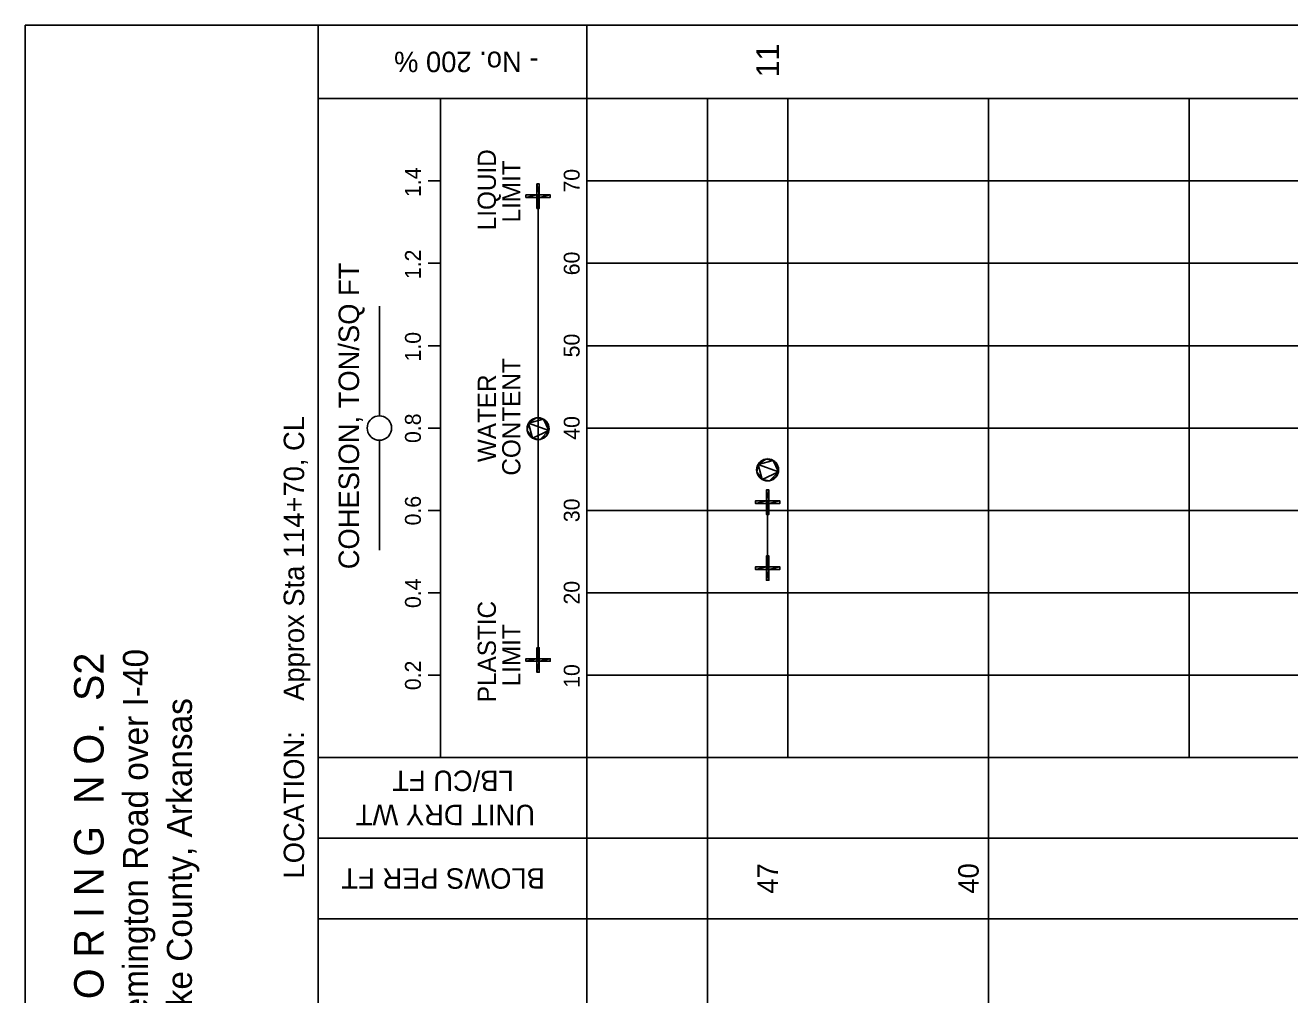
# Model space of a CAD drawing. Extents: x 1313964 to 1316843, y 2087046 to 2096619.
# Drawn here: x 1314075.31 to 1314106.79, y 2089946.89 to 2089971.04 of the extents above; entities that cross this region are included whole.
import ezdxf

# ---------------------------------------------------------------- set-up
doc = ezdxf.new("R2010")
doc.units = 0
doc.layers.add('B-Sub-Contour', color=7, linetype='Continuous')
doc.layers.add('Default', color=7, linetype='Continuous')

# ---------------------------------------------------------------- blocks, each defined once
blk = doc.blocks.new('POINT_DISPLAY')
at = {"layer": 'Default'}
blk.add_line((0, 0), (0, 0), dxfattribs=at)
blk = doc.blocks.new('DMK_101')
at = {"layer": 'Default'}
for points in [[(-14269.212, 2386.584), (-14476.476, 0), (-14269.212, -2386.584), (-14269.212, 2386.584)], [(-12638.532, 6858), (-13653.516, 4690.872), (-14269.212, 2386.584), (-12638.532, 6858)], [(-12638.532, 6858), (-14269.212, 2386.584), (-14269.212, -2386.584), (-12638.532, 6858)], [(-12638.532, 6858), (-14269.212, -2386.584), (-3147.06, -13508.736), (-12638.532, 6858)], [(-3147.06, 13511.784), (-7618.476, 11878.056), (-12638.532, 6858), (-3147.06, 13511.784)], [(6097.524, 11878.056), (-3147.06, 13511.784), (-12638.532, 6858), (6097.524, 11878.056)], [(-7618.476, 11878.056), (-11266.932, 8820.912), (-12638.532, 6858), (-7618.476, 11878.056)], [(-3147.06, -13508.736), (6097.524, 11878.056), (-12638.532, 6858), (-3147.06, -13508.736)], [(-7618.476, 11878.056), (-9578.34, 10506.456), (-11266.932, 8820.912), (-7618.476, 11878.056)], [(-9578.34, 10506.456), (-10456.164, 9698.736), (-11266.932, 8820.912), (-9578.34, 10506.456)], [(-3147.06, 13511.784), (-5451.348, 12893.04), (-7618.476, 11878.056), (-3147.06, 13511.784)], [(1626.108, 13511.784), (-760.476, 13712.952), (-3147.06, 13511.784), (1626.108, 13511.784)], [(6097.524, 11878.056), (1626.108, 13511.784), (-3147.06, 13511.784), (6097.524, 11878.056)], [(-3147.06, -13508.736), (11117.58, -6858), (6097.524, 11878.056), (-3147.06, -13508.736)], [(6097.524, 11878.056), (3930.396, 12893.04), (1626.108, 13511.784), (6097.524, 11878.056)], [(11117.58, 6858), (8060.436, 10506.456), (6097.524, 11878.056), (11117.58, 6858)], [(12751.308, 2386.584), (11117.58, 6858), (6097.524, 11878.056), (12751.308, 2386.584)], [(11117.58, -6858), (12751.308, 2386.584), (6097.524, 11878.056), (11117.58, -6858)], [(9745.98, 8820.912), (8938.26, 9698.736), (8060.436, 10506.456), (9745.98, 8820.912)], [(11117.58, 6858), (9745.98, 8820.912), (8060.436, 10506.456), (11117.58, 6858)], [(12751.308, 2386.584), (12132.564, 4690.872), (11117.58, 6858), (12751.308, 2386.584)], [(11117.58, -6858), (12751.308, -2386.584), (12751.308, 2386.584), (11117.58, -6858)], [(12751.308, -2386.584), (12952.476, 0), (12751.308, 2386.584), (12751.308, -2386.584)], [(-14269.212, -2386.584), (-13653.516, -4690.872), (-12638.532, -6858), (-14269.212, -2386.584)], [(-14269.212, -2386.584), (-12638.532, -6858), (-9578.34, -10506.456), (-14269.212, -2386.584)], [(-14269.212, -2386.584), (-9578.34, -10506.456), (-3147.06, -13508.736), (-14269.212, -2386.584)], [(-12638.532, -6858), (-11266.932, -8817.864), (-9578.34, -10506.456), (-12638.532, -6858)], [(-11266.932, -8817.864), (-10456.164, -9695.688), (-9578.34, -10506.456), (-11266.932, -8817.864)], [(-9578.34, -10506.456), (-7618.476, -11878.056), (-3147.06, -13508.736), (-9578.34, -10506.456)], [(-7618.476, -11878.056), (-5451.348, -12893.04), (-3147.06, -13508.736), (-7618.476, -11878.056)], [(-3147.06, -13508.736), (6097.524, -11878.056), (11117.58, -6858), (-3147.06, -13508.736)], [(-3147.06, -13508.736), (1626.108, -13508.736), (6097.524, -11878.056), (-3147.06, -13508.736)], [(-3147.06, -13508.736), (-760.476, -13716), (1626.108, -13508.736), (-3147.06, -13508.736)], [(1626.108, -13508.736), (3930.396, -12893.04), (6097.524, -11878.056), (1626.108, -13508.736)], [(6097.524, -11878.056), (8060.436, -10506.456), (11117.58, -6858), (6097.524, -11878.056)], [(8060.436, -10506.456), (9745.98, -8817.864), (11117.58, -6858), (8060.436, -10506.456)], [(8060.436, -10506.456), (8938.26, -9695.688), (9745.98, -8817.864), (8060.436, -10506.456)], [(11117.58, -6858), (12132.564, -4690.872), (12751.308, -2386.584), (11117.58, -6858)]]:
    blk.add_lwpolyline(points, close=True, dxfattribs=at)
blk.add_blockref('POINT_DISPLAY', (14479.524, 0), dxfattribs=at)
blk = doc.blocks.new('DMK_99')
at = {"layer": 'Default'}
for points in [[(-1524, -1524), (-1524, 1524), (-15240, 1524), (-1524, -1524)], [(-1524, -1524), (-15240, 1524), (-15240, -1524), (-1524, -1524)], [(1524, 1524), (1524, 15240), (-1524, 15240), (1524, 1524)], [(1524, 1524), (-1524, 15240), (-1524, 1524), (1524, 1524)], [(-1524, -1524), (1524, -1524), (1524, 1524), (-1524, -1524)], [(-1524, -1524), (1524, 1524), (-1524, 1524), (-1524, -1524)], [(1524, -1524), (15240, -1524), (15240, 1524), (1524, -1524)], [(1524, -1524), (15240, 1524), (1524, 1524), (1524, -1524)], [(-1524, -1524), (-1524, -15240), (1524, -15240), (-1524, -1524)], [(-1524, -1524), (1524, -15240), (1524, -1524), (-1524, -1524)]]:
    blk.add_lwpolyline(points, close=True, dxfattribs=at)
blk = doc.blocks.new('DMK_7')
at = {"layer": 'Default'}
blk.add_lwpolyline([(0, -15240), (2651.76, -15011.4), (5212.08, -14325.6), (7620, -13197.84), (9799.32, -11673.84), (10774.68, -10774.68), (11673.84, -9799.32), (13197.84, -7620), (14325.6, -5212.08), (15011.4, -2651.76), (15240, 0), (15011.4, 2651.76), (14325.6, 5212.08), (13197.84, 7620), (11673.84, 9799.32), (10774.68, 10774.68), (9799.32, 11673.84), (7620, 13197.84), (5212.08, 14325.6), (2651.76, 15011.4), (0, 15240), (-2651.76, 15011.4), (-5212.08, 14325.6), (-7620, 13197.84), (-9799.32, 11673.84), (-10774.68, 10774.68), (-11673.84, 9799.32), (-13197.84, 7620), (-14325.6, 5212.08), (-15011.4, 2651.76), (-15240, 0), (-15011.4, -2651.76), (-14325.6, -5212.08), (-13197.84, -7620), (-11673.84, -9799.32), (-10774.68, -10774.68), (-9799.32, -11673.84), (-7620, -13197.84), (-5212.08, -14325.6), (-2651.76, -15011.4), (0, -15240)], dxfattribs=at)

msp = doc.modelspace()

# ---------------------------------------------------------------- linework, layer by layer
at = {"layer": 'B-Sub-Contour'}
for points in [[(1314136.725, 2089928.164), (1314136.725, 2089971.035), (1314075.306, 2089971.035), (1314075.306, 2089928.164), (1314136.725, 2089928.164)], [(1314082.603, 2089928.164), (1314082.603, 2089971.035)], [(1314089.292, 2089928.164), (1314089.292, 2089971.035)], [(1314134.292, 2089969.211), (1314082.603, 2089969.211)], [(1314085.644, 2089969.211), (1314085.34, 2089969.211)], [(1314085.644, 2089952.792), (1314085.644, 2089969.211)], [(1314134.292, 2089969.211), (1314089.292, 2089969.211)], [(1314089.292, 2089952.792), (1314089.292, 2089969.211)], [(1314092.292, 2089948.779), (1314092.292, 2089969.211)], [(1314094.292, 2089952.792), (1314094.292, 2089969.211)], [(1314099.292, 2089948.779), (1314099.292, 2089969.211)], [(1314099.292, 2089952.792), (1314099.292, 2089969.211)], [(1314104.292, 2089952.792), (1314104.292, 2089969.211)], [(1314085.644, 2089967.159), (1314085.34, 2089967.159)], [(1314134.292, 2089967.159), (1314089.292, 2089967.159)], [(1314088.076, 2089955.225), (1314088.076, 2089966.779)], [(1314085.644, 2089965.106), (1314085.34, 2089965.106)], [(1314134.292, 2089965.106), (1314089.292, 2089965.106)], [(1314084.124, 2089961.306), (1314084.124, 2089964.042)], [(1314085.644, 2089963.054), (1314085.34, 2089963.054)], [(1314134.292, 2089963.054), (1314089.292, 2089963.054)], [(1314085.644, 2089961.002), (1314085.34, 2089961.002)], [(1314134.292, 2089961.002), (1314089.292, 2089961.002)], [(1314084.124, 2089957.961), (1314084.124, 2089960.698)], [(1314085.644, 2089958.949), (1314085.34, 2089958.949)], [(1314134.292, 2089958.949), (1314089.292, 2089958.949)], [(1314093.792, 2089957.513), (1314093.792, 2089959.155)], [(1314093.792, 2089957.513), (1314093.792, 2089959.155)], [(1314085.644, 2089956.897), (1314085.34, 2089956.897)], [(1314134.292, 2089956.897), (1314089.292, 2089956.897)], [(1314085.644, 2089954.845), (1314085.34, 2089954.845)], [(1314134.292, 2089954.845), (1314089.292, 2089954.845)], [(1314134.292, 2089952.792), (1314082.603, 2089952.792)], [(1314085.644, 2089952.792), (1314085.34, 2089952.792)], [(1314134.292, 2089952.792), (1314089.292, 2089952.792)], [(1314134.292, 2089950.785), (1314082.603, 2089950.785)], [(1314134.292, 2089948.779), (1314082.603, 2089948.779)], [(1314092.292, 2089932.907), (1314092.292, 2089948.779)], [(1314099.292, 2089932.907), (1314099.292, 2089948.779)]]:
    msp.add_lwpolyline(points, dxfattribs=at)

# ---------------------------------------------------------------- block references
at = {"layer": 'B-Sub-Contour', "xscale": 1.9951013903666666e-05, "yscale": 1.9951013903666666e-05, "rotation": 90}
for name, p in [('DMK_99', (1314088.076, 2089966.779)), ('DMK_7', (1314084.124, 2089961.002)), ('DMK_101', (1314088.076, 2089961.002)), ('DMK_101', (1314093.792, 2089959.975)), ('DMK_101', (1314093.792, 2089959.975)), ('DMK_99', (1314093.792, 2089959.155)), ('DMK_99', (1314093.792, 2089959.155)), ('DMK_99', (1314093.792, 2089957.513)), ('DMK_99', (1314093.792, 2089957.513)), ('DMK_99', (1314088.076, 2089955.225))]:
    msp.add_blockref(name, p, dxfattribs=at)

# ---------------------------------------------------------------- texts
at = {"layer": 'B-Sub-Contour'}
for s, height, rotation, p in [('- No. 200 %', 0.50899, 180, (1314088.084, 2089970.378)), ('11', 0.5655, 90, (1314094.075, 2089969.738)), ('LIQUID', 0.4524, 90, (1314087.025, 2089965.93)), ('1.4', 0.3959, 90, (1314085.157, 2089966.757)), ('LIMIT', 0.4524, 90, (1314087.634, 2089966.123)), ('70', 0.3959, 90, (1314089.11, 2089966.868)), ('1.2', 0.3959, 90, (1314085.157, 2089964.712)), ('60', 0.3959, 90, (1314089.11, 2089964.808)), ('COHESION, TON/SQ FT', 0.50899, 90, (1314083.618, 2089957.485)), ('1.0', 0.3959, 90, (1314085.157, 2089962.66)), ('50', 0.3959, 90, (1314089.11, 2089962.763)), ('CONTENT', 0.4524, 90, (1314087.634, 2089959.817)), ('WATER', 0.4524, 90, (1314087.025, 2089960.153)), ('LOCATION:    Approx Sta 114+70, CL', 0.50899, 90, (1314082.25, 2089949.782)), ('0.8', 0.3959, 90, (1314085.157, 2089960.63)), ('40', 0.3959, 90, (1314089.11, 2089960.711)), ('0.6', 0.3959, 90, (1314085.157, 2089958.577)), ('30', 0.3959, 90, (1314089.11, 2089958.658)), ('0.4', 0.3959, 90, (1314085.157, 2089956.518)), ('20', 0.3959, 90, (1314089.11, 2089956.606)), ('PLASTIC', 0.4524, 90, (1314087.025, 2089954.174)), ('LIMIT', 0.4524, 90, (1314087.634, 2089954.569)), ('L O G  O F  B O R I N G  N O.  S2', 0.7352, 90, (1314077.257, 2089940.493)), ('061610 - Remington Road over I-40', 0.62209, 90, (1314078.361, 2089942.229)), ('0.2', 0.3959, 90, (1314085.157, 2089954.473)), ('10', 0.3959, 90, (1314089.11, 2089954.531)), ('Lonoke County, Arkansas', 0.62209, 90, (1314079.455, 2089944.747)), ('LB/CU FT', 0.509, 180, (1314087.47, 2089952.469)), ('UNIT DRY WT', 0.50899, 180, (1314087.999, 2089951.618)), ('40', 0.509, 90, (1314099.047, 2089949.404)), ('BLOWS PER FT', 0.50899, 180, (1314088.245, 2089950.037)), ('47', 0.509, 90, (1314094.047, 2089949.404))]:
    msp.add_text(s, height=height, rotation=rotation, dxfattribs=at).set_placement(p)

doc.saveas('drawing.dxf')
